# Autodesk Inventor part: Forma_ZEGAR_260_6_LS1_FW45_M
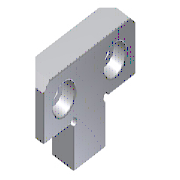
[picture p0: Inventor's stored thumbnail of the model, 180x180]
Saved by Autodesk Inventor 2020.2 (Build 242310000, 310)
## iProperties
Manager: www.cadconsulting.pl
Company: Fabian Stasiak CAD Consulting
Created: 2014-02
Part Number: Forma_ZEGAR_260_6_LS1_FW45_M
Material: 1.7131
Description: Straight interlocks
Document SubType Name: Modeling
Designer: F.Stasiak
Standard Revision: 1
Manufacturer: DME
Language: pl-PL
Size Designation: 50
Categories: <MemberInstance><Categories><Category DisplayName="Forma wtryskowa" InternalName="349578f2-f4d4-4954-8c09-8e99297a61c0" Mnemonic="MOLD"><Category DisplayName="E
Density: 7.85 g/cm^3
Appearance: Domyślna
Catalog Web Link: www.expertbooks.pl
IsCustomPart: 1
Author: F.Stasiak
Subject: Zbiór ćwiczeń. Autodesk Inventor 2020. Kurs Professional
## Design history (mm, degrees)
sketch "Sketch1"
  geometry: L1 (-11, 0)-(-25, 0); L2 (-25, 0)-(-25, 17); L3 (-25, 17)-(25, 17); L4 (25, 17)-(25, 0); L5 (25, 0)-(11, 0); L6 (10, -1)-(10, -18); L7 (10, -18)-(-10, -18); L8 (-10, -18)-(-10, -1); L9 (0, 23.2)-(0, -20.2) reference; L10 (-28, 0)-(28, 0) reference; A1 r 1 centre (-10, 0) between (-10, -1) and (-11, 0); A2 r 1 centre (10, 0) between (11, 0) and (10, -1); 1 further point
  constraints: 16 end point, 6 point on line, 4 parallel, 4 point on circle, 3 collinear, 2 centre point, 1 horizontal, 1 perpendicular, 1 vertical, 2 other
  dimensions: "d0" = 50 distance between parallel lines of L2 L4 (= b); "d1" = 17 distance between parallel lines of L3 L1 (= s_); "d2" = 35 distance between parallel lines of L3 L7 (= l_); "d3" = 20 distance between parallel lines of L8 L6 (= b1); "d6" = 2 diameter of A1 (= R3); "d7" = 2 diameter of A2 (= R3)
extrude "Extrusion1" new body sketch "Sketch1" distance "d4" = 12.5 (= h_); taper "d5" = 0 deg
sketch "Sketch2"
  geometry: L1 (-17, 25)-(-17, -25) reference; L2 (0, 0)-(-21.442, 0); 2 further points
  constraints: 2 end point, 1 perpendicular, 1 symmetric about line
  dimensions: "d8" = 8.5 distance from line of L1 point (-8.5, 16) (= a1); "d10" = 32 distance of point (-8.5, 16) point (-8.5, -16) (= b2)
hole "Hole1" sketch "Sketch2" diameter "d11" = 6.6 (= D2); stored, may be unused: countersink angle "d15" = 90 deg, drill point angle "d17" = 0 deg; dims "d12" = 6, "d13" = 11 (= D1), "d14" = 6 (= M), "d16" = 12.5 (= h_)
hole "Hole2" sketch "Sketch2" diameter "d36" = 6.6 (= D2); stored, may be unused: countersink angle "d40" = 90 deg, drill point angle "d42" = 0 deg; dims "d37" = 6, "d38" = 11 (= D1), "d39" = 6 (= M), "d41" = 12.5 (= h_)
chamfer "Chamfer1" distance "d18" = 3 (= f1); stored, may be unused: second distance "d19" = 2, angle "d20" = 45 deg
chamfer "Chamfer2" distance "d21" = 6.5 (= f_); stored, may be unused: second distance "d22" = 2, angle "d23" = 45 deg
sketch "Sketch4"
  geometry: L1 (-18, 10)-(0, 10); L2 (0, 10)-(0, -10); L3 (0, -10)-(-18, -10); L4 (-18, -10)-(-18, 10); L5 (-18, 10)-(-1, 10) reference; L6 (-18, -10)-(-18, 10) reference; L7 (-1, -10)-(-18, -10) reference; L8 (0, 11)-(0, 18.5) reference; 1 further point
  constraints: 8 end point, 4 collinear, 2 parallel, 1 horizontal, 1 perpendicular
extrude "Extrusion2" cut sketch "Sketch4" distance "d24" = 1 (= h05); taper "d25" = 0 deg
fillet "Fillet1" dims "d26" = 0.5 (= 0.5 x h05)
sketch "Sketch5"
  geometry: L1 (14, 25)-(0.5, 25) reference; L2 (17, -19)-(17, 19) reference; L3 (0.5, -25)-(14, -25) reference; L4 (-18, 9.5)-(-18, -9.5) reference; L5 (-18, 25)-(17, 25); L6 (17, 25)-(17, -25); L7 (17, -25)-(-18, -25); L8 (-18, -25)-(-18, 25); 1 further point
  constraints: 8 end point, 4 collinear, 2 parallel, 1 horizontal, 1 perpendicular
extrude_surface "ExtrusionSrf1" sketch "Sketch5" dims "d27" = 25 (= 2 x h_), "d28" = 0
fillet "Fillet2" dims "d29" = 2 (= R3)
feature "Stitch Surface1" dims "d43" = 0.254 (derived)
body "Solid1"
body "Srf1"
body "Srf2"
body "Srf3"
body "Srf4"
patch "Boundary Patch1" dims "d30" = 0, "d31" = 0, "d32" = 0
patch "Boundary Patch2" dims "d33" = 0, "d34" = 0, "d35" = 0
other parameters: "b" = 50 [user parameter; used in 1 equation term], "a1" = 8.5 [user parameter; used in 1 equation term], "b1" = 20 [user parameter; used in 1 equation term], "b2" = 32 [user parameter; used in 1 equation term], "f_" = 6.5 [user parameter; used in 1 equation term], "f1" = 3 [user parameter; used in 1 equation term], "h_" = 12.5 [user parameter; used in 4 equation terms], "l_" = 35 [user parameter; used in 1 equation term], "s_" = 17 [user parameter; used in 1 equation term], "D1" = 11 [user parameter; used in 2 equation terms], "D2" = 6.6 [user parameter; used in 2 equation terms], "M" = 6 [user parameter; used in 2 equation terms], "h05" = 1 [user parameter; used in 2 equation terms], "R3" = 2 [user parameter; used in 3 equation terms]
